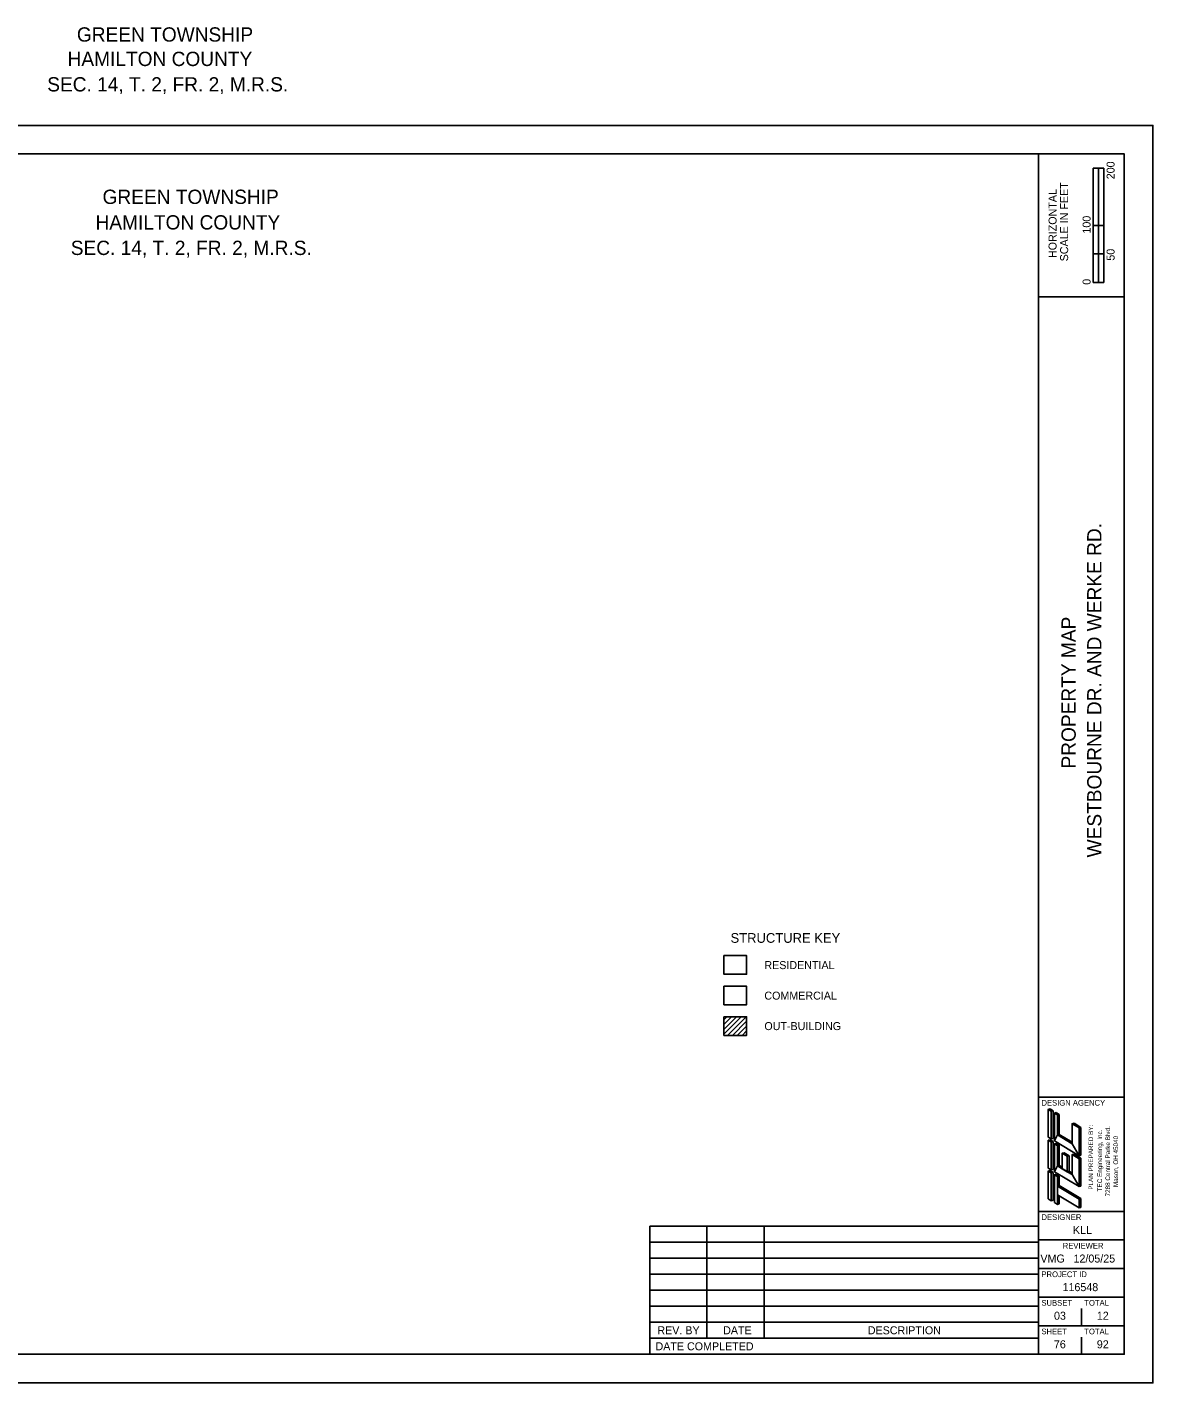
# Model space of a CAD drawing. Extents: x -2.7 to 34, y 0 to 23.7.
# Drawn here: x 14.3 to 34, y 0 to 23.72 of the extents above; entities that cross this region are included whole.
import ezdxf

# ---------------------------------------------------------------- set-up
doc = ezdxf.new("R2010")
doc.units = 0
for name, color, linetype in [('0_Match_Line_Mask', 7, 'Continuous'), ('0_Mview', 7, 'Continuous'), ('0_Surface_Temp', 7, 'Continuous'), ('0_View_Frame_Border', 7, 'Continuous'), ('0_View_Frame_Border_Text', 7, 'Continuous'), ('AP_P_Airside', 7, 'Continuous')]:
    doc.layers.add(name, color=color, linetype=linetype)

msp = doc.modelspace()

# ---------------------------------------------------------------- linework, layer by layer
at = {"layer": '0_Match_Line_Mask'}
msp.add_lwpolyline([(0, 0), (34, 0), (34, 22), (0, 22)], close=True, dxfattribs=at)
at = {"layer": '0_Mview'}
for p, q in [((32, 0.5), (32, 21.5)), ((32, 19), (33.5, 19)), ((32, 5), (33.5, 5)), ((32, 3), (33.5, 3)), ((32, 2.5), (33.5, 2.5)), ((32, 2), (33.5, 2)), ((32, 1.5), (33.5, 1.5)), ((32, 1), (33.5, 1))]:
    msp.add_line(p, q, dxfattribs=at)
msp.add_lwpolyline([(1.5, 21.5), (33.5, 21.5), (33.5, 0.5), (1.5, 0.5)], close=True, dxfattribs=at)
at = {"layer": '0_Surface_Temp'}
for p, q in [((32.957, 19.25), (32.957, 21.25)), ((33.144, 21.25), (32.957, 21.25)), ((32.957, 20.25), (32.957, 21.25)), ((32.957, 21.25), (33.05, 21.25)), ((33.05, 21.25), (33.051, 21.25)), ((33.051, 21.25), (33.051, 20.25)), ((33.144, 21.25), (33.144, 19.25)), ((33.051, 20.25), (32.957, 20.25)), ((33.143, 20.25), (33.05, 20.25)), ((33.05, 20.25), (33.05, 19.75)), ((33.143, 19.75), (33.143, 20.25)), ((33.05, 19.75), (32.957, 19.75)), ((32.957, 19.75), (32.957, 19.25)), ((33.05, 19.25), (33.05, 19.75)), ((33.05, 19.75), (33.143, 19.75)), ((33.144, 19.25), (32.957, 19.25)), ((32.957, 19.25), (33.05, 19.25)), ((32.75, 4), (32.75, 4)), ((32.75, 1), (32.75, 1.3)), ((32.75, 0.5), (32.75, 0.8)), ((32.375, 0.675), (32.375, 0.675))]:
    msp.add_line(p, q, dxfattribs=at)
at = {"layer": '0_View_Frame_Border'}
for p, q in [((26.493, 6.403), (26.494, 6.404)), ((26.493, 6.353), (26.544, 6.404)), ((26.493, 6.268), (26.629, 6.404)), ((26.493, 6.184), (26.713, 6.404)), ((26.493, 6.099), (26.798, 6.404)), ((26.557, 6.079), (26.883, 6.404)), ((26.642, 6.079), (26.89, 6.327)), ((26.726, 6.079), (26.89, 6.242)), ((26.493, 6.083), (26.497, 6.079)), ((26.811, 6.079), (26.89, 6.157)), ((32.169, 4.785), (32.201, 4.794)), ((32.169, 4.299), (32.169, 4.785)), ((32.223, 4.753), (32.169, 4.785)), ((32.255, 4.761), (32.201, 4.794)), ((32.223, 4.753), (32.255, 4.761)), ((32.223, 4.267), (32.223, 4.753)), ((32.255, 4.275), (32.255, 4.761)), ((32.277, 4.721), (32.309, 4.729)), ((32.331, 4.688), (32.277, 4.721)), ((32.277, 4.235), (32.277, 4.721)), ((32.309, 4.729), (32.363, 4.696)), ((32.331, 4.688), (32.363, 4.696)), ((32.331, 4.337), (32.331, 4.688)), ((32.363, 4.696), (32.363, 4.345)), ((32.587, 4.534), (32.62, 4.542)), ((32.587, 4.183), (32.587, 4.534)), ((32.709, 4.461), (32.587, 4.534)), ((32.62, 4.542), (32.741, 4.47)), ((32.223, 4.267), (32.169, 4.299)), ((32.223, 4.267), (32.255, 4.275)), ((32.331, 4.337), (32.363, 4.345)), ((32.587, 4.183), (32.331, 4.337)), ((32.363, 4.345), (32.587, 4.211)), ((32.709, 4.461), (32.741, 4.47)), ((32.709, 3.975), (32.709, 4.461)), ((32.741, 4.47), (32.741, 3.984)), ((32.169, 4.245), (32.201, 4.254)), ((32.169, 3.759), (32.169, 4.245)), ((32.223, 4.213), (32.169, 4.245)), ((32.255, 4.222), (32.201, 4.254)), ((32.223, 4.213), (32.255, 4.222)), ((32.223, 3.727), (32.223, 4.213)), ((32.255, 3.736), (32.255, 4.222)), ((32.709, 3.975), (32.277, 4.235)), ((32.277, 4.181), (32.309, 4.189)), ((32.277, 3.695), (32.277, 4.181)), ((32.331, 4.148), (32.277, 4.181)), ((32.309, 4.189), (32.363, 4.156)), ((32.331, 4.148), (32.363, 4.156)), ((32.331, 3.797), (32.331, 4.148)), ((32.363, 4.156), (32.363, 3.805)), ((32.331, 3.797), (32.363, 3.805)), ((32.415, 3.747), (32.331, 3.797)), ((32.363, 3.805), (32.415, 3.774)), ((32.415, 4.019), (32.448, 4.027)), ((32.415, 4.019), (32.415, 3.747)), ((32.415, 4.019), (32.503, 3.966)), ((32.448, 4.027), (32.535, 3.974)), ((32.503, 3.966), (32.535, 3.974)), ((32.503, 3.966), (32.503, 3.694)), ((32.535, 3.974), (32.535, 3.702)), ((32.587, 3.994), (32.62, 4.002)), ((32.587, 3.643), (32.587, 3.994)), ((32.709, 3.921), (32.587, 3.994)), ((32.62, 4.002), (32.741, 3.93)), ((32.709, 3.975), (32.741, 3.984)), ((32.709, 3.921), (32.741, 3.93)), ((32.709, 3.435), (32.709, 3.921)), ((32.741, 3.93), (32.741, 3.444)), ((32.223, 3.727), (32.169, 3.759)), ((32.169, 3.705), (32.201, 3.715)), ((32.169, 3.219), (32.169, 3.705)), ((32.223, 3.673), (32.169, 3.705)), ((32.255, 3.681), (32.201, 3.715)), ((32.222, 3.673), (32.255, 3.681)), ((32.223, 3.727), (32.255, 3.736)), ((32.223, 3.187), (32.223, 3.673)), ((32.255, 3.195), (32.255, 3.681)), ((32.709, 3.435), (32.277, 3.695)), ((32.277, 3.641), (32.309, 3.651)), ((32.331, 3.608), (32.277, 3.641)), ((32.277, 3.155), (32.277, 3.641)), ((32.309, 3.651), (32.363, 3.616)), ((32.331, 3.608), (32.363, 3.616)), ((32.331, 3.444), (32.331, 3.608)), ((32.363, 3.616), (32.363, 3.452)), ((32.503, 3.694), (32.535, 3.702)), ((32.587, 3.643), (32.503, 3.694)), ((32.535, 3.702), (32.587, 3.671)), ((32.331, 3.444), (32.363, 3.452)), ((32.331, 3.444), (32.709, 3.217)), ((32.363, 3.452), (32.741, 3.225)), ((32.709, 3.435), (32.741, 3.444)), ((32.223, 3.187), (32.169, 3.219)), ((32.223, 3.187), (32.255, 3.195)), ((32.331, 3.122), (32.277, 3.155)), ((32.331, 3.287), (32.709, 3.06)), ((32.331, 3.122), (32.331, 3.287)), ((32.331, 3.122), (32.363, 3.13)), ((32.363, 3.13), (32.363, 3.267)), ((32.709, 3.217), (32.741, 3.225)), ((32.709, 3.06), (32.709, 3.217)), ((32.741, 3.225), (32.741, 3.068)), ((32.709, 3.06), (32.741, 3.068)), ((25.197, 2.74), (25.197, 0.5)), ((25.197, 2.74), (32, 2.74)), ((26.197, 2.74), (26.197, 0.78)), ((27.197, 2.74), (27.197, 0.78)), ((25.197, 2.46), (32, 2.46)), ((25.197, 2.18), (32, 2.18)), ((25.197, 1.9), (32, 1.9)), ((25.197, 1.62), (32, 1.62)), ((25.197, 1.34), (32, 1.34)), ((25.197, 1.06), (32, 1.06)), ((25.197, 0.78), (32, 0.78)), ((32, 0.5), (32, 0.5))]:
    msp.add_line(p, q, dxfattribs=at)
for points in [[(26.493, 7.475), (26.89, 7.475), (26.89, 7.149), (26.493, 7.149)], [(26.493, 6.404), (26.89, 6.404), (26.89, 6.079), (26.493, 6.079)], [(32.169, 4.299), (32.223, 4.267), (32.223, 4.753), (32.169, 4.785)], [(32.277, 4.235), (32.331, 4.337), (32.331, 4.688), (32.277, 4.721)], [(32.709, 3.975), (32.587, 4.183), (32.587, 4.534), (32.709, 4.461)], [(32.277, 4.235), (32.331, 4.337), (32.587, 4.183), (32.709, 3.975)], [(32.169, 3.759), (32.223, 3.727), (32.223, 4.213), (32.169, 4.245)], [(32.277, 3.695), (32.331, 3.797), (32.331, 4.148), (32.277, 4.181)], [(32.277, 3.695), (32.331, 3.797), (32.587, 3.643), (32.709, 3.435)], [(32.415, 3.747), (32.415, 4.019), (32.503, 3.966), (32.503, 3.694)], [(32.709, 3.435), (32.587, 3.643), (32.587, 3.994), (32.709, 3.921)], [(32.169, 3.219), (32.223, 3.187), (32.223, 3.673), (32.169, 3.705)], [(32.277, 3.155), (32.331, 3.122), (32.331, 3.608), (32.277, 3.641)], [(32.331, 3.287), (32.331, 3.444), (32.709, 3.217), (32.709, 3.06)]]:
    msp.add_lwpolyline(points, close=True, dxfattribs=at)
at = {"layer": 'AP_P_Airside'}
msp.add_lwpolyline([(26.493, 6.614), (26.89, 6.614), (26.89, 6.94), (26.493, 6.94)], close=True, dxfattribs=at)

# ---------------------------------------------------------------- texts
for s, p in [('PLAN PREPARED BY:', (32.954, 3.38)), ('TEC Engineering, Inc.', (33.11, 3.351)), ('7288 Central Parke Blvd.', (33.25, 3.262)), ('Mason, OH 45040', (33.39, 3.425))]:
    msp.add_text(s, height=0.08, rotation=90).set_placement(p)
at = {"layer": '0_Surface_Temp'}
for s, height, p in [('200', 0.14, (33.33, 21.057)), ('HORIZONTAL', 0.14, (32.315, 19.679)), ('SCALE IN FEET', 0.14, (32.517, 19.621)), ('100', 0.14, (32.91, 20.107)), ('50', 0.14, (33.33, 19.633)), ('0', 0.14, (32.91, 19.211)), ('WESTBOURNE DR. AND WERKE RD.', 0.25, (33.1, 9.193)), ('PROPERTY MAP', 0.25, (32.65, 10.748))]:
    msp.add_text(s, height=height, rotation=90, dxfattribs=at).set_placement(p)
for s, height, p in [('GREEN TOWNSHIP', 0.25, (15.622, 20.625)), ('HAMILTON COUNTY', 0.25, (15.499, 20.178)), ('SEC. 14, T. 2, FR. 2, M.R.S.', 0.25, (15.066, 19.732)), ('DESIGN AGENCY', 0.1, (32.05, 4.85)), ('DESIGNER', 0.1, (32.05, 2.85)), ('KLL', 0.14, (32.601, 2.605)), ('REVIEWER', 0.1, (32.422, 2.35)), ('VMG', 0.14, (32.032, 2.105)), ('12/05/25', 0.14, (32.611, 2.105)), ('PROJECT ID', 0.1, (32.05, 1.85)), ('116548', 0.14, (32.419, 1.605)), ('SUBSET', 0.1, (32.05, 1.35)), ('TOTAL', 0.1, (32.8, 1.35)), ('03', 0.14, (32.27, 1.105)), ('12', 0.14, (33.019, 1.105)), ('SHEET', 0.1, (32.05, 0.85)), ('TOTAL', 0.1, (32.8, 0.85)), ('76', 0.14, (32.268, 0.605)), ('92', 0.14, (33.019, 0.605))]:
    msp.add_text(s, height=height, dxfattribs=at).set_placement(p)
at = {"layer": '0_View_Frame_Border'}
for s, height, p in [('STRUCTURE KEY', 0.17, (26.61, 7.699)), ('RESIDENTIAL', 0.14, (27.202, 7.239)), ('COMMERCIAL', 0.14, (27.202, 6.705)), ('OUT-BUILDING', 0.14, (27.202, 6.172)), ('REV. BY', 0.14, (25.33, 0.85)), ('DATE', 0.14, (26.48, 0.85)), ('DESCRIPTION', 0.14, (29.012, 0.85)), ('DATE COMPLETED', 0.14, (25.297, 0.57))]:
    msp.add_text(s, height=height, dxfattribs=at).set_placement(p)
at = {"layer": '0_View_Frame_Border_Text'}
for s, p in [('GREEN TOWNSHIP', (15.173, 23.465)), ('HAMILTON COUNTY', (15.01, 23.038)), ('SEC. 14, T. 2, FR. 2, M.R.S.', (14.654, 22.593))]:
    msp.add_text(s, height=0.25, dxfattribs=at).set_placement(p)

doc.saveas('drawing.dxf')
